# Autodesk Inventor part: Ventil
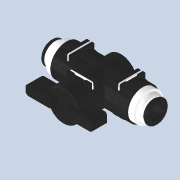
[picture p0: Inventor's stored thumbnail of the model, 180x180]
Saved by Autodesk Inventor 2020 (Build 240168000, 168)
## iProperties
Created: 2025-03
Part Number: Ventil
Material: Všeobecné
Document SubType Name: Modeling
Designer: doma
Density: 1 g/cm^3
Appearance: Výchozí
Title: raccordo 6mm v5.step
Sending System: Autodesk Translation Framework v13.20.0.188
Preprocessor: ST-DEVELOPER v20
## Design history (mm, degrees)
feature "Connector self locking 6mm v1_1:1"
feature "Connector self locking 6mm v1_1:2"
feature "Connector self locking 6mm v1_1:3"
feature "Connector self locking 6mm v1_1:4"
feature "Connector self locking 6mm v1_1:5"
feature "Connector self locking 6mm v1_1:6"
feature "Connector self locking 6mm v1_1:7"
feature "Connector self locking 6mm v1_1:8"
feature "Connector self locking 6mm v1_1:9"
feature "Connector self locking 6mm v1_1:10"
feature "Connector self locking 6mm v1_1:11"
node "Upravit přímo1"
node "Těleso1"
node "Těleso2"
node "Těleso3"
node "Těleso4"
node "Těleso5"
node "Těleso6"
node "Těleso7"
node "Těleso8"
node "Těleso9"
node "Těleso10"
node "Těleso11"
feature "Měřítko1"
other parameters: "d0" = 16.63961
